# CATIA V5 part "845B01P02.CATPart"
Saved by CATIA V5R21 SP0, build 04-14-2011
Part number: 845B01P01
Bounding box of the stored display mesh (mm): x -25.75 to 25.25, y -25.549 to 25.54, z -6.5 to 6.5
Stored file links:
  C:\Users\ALI OZGUN\Desktop\alhan\845B01P02.CATPart
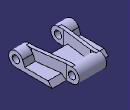
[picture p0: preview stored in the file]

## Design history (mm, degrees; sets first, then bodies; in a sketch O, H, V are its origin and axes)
Body1 (main body)
  Sketch1 on yz-plane, origin (0, 0, 0), H (0, 1, 0), V (0, 0, 1)
    construction line L1 (-19.05, 0) -> (19.05, 0)
    point P1 (-19.05, 0)
    point P2 (19.05, 0)
    line L2 (-19.05, 6.5) -> (19.05, 6.5)
    line L3 (19.05, -6.5) -> (-19.05, -6.5)
    arc A1 centre (19.05, 0) radius 6.5 from (19.05, 6.5) to (19.05, -6.5) cw
    arc A2 centre (-19.05, 0) radius 6.5 from (-19.05, -6.5) to (-19.05, 6.5) cw
    circle A3 centre (19.05, 0) radius 3.25
    circle A4 centre (-19.05, 0) radius 3.25
    distance L1 L2 = 6.5
    length L1 = 38.1
    distance P2 V = 19.05
    radius A3 = 3.25
    radius A4 = 3.25
    coincidence: P1 H
    horizontal: L1 H
    tangency: A1 L2, A2 L2, A1 L3, A2 L3
  Pad1: profile Sketch1, direction (1, 0, 0), length 76.5, mirrored extent
  Sketch2 on face of Pad1 from Sketch1.L2, origin (0, 0, 6.5), H (1, 0, 0), V (0, 1, 0)
    line L1 (38, -14) -> (64, -14)
    line L2 (64, -14) -> (64, -36.0786)
    line L3 (64, -36.0786) -> (38, -36.0786)
    line L4 (38, -36.0786) -> (38, -14)
    line L5 (-13, -14) -> (13, -14)
    line L6 (13, -14) -> (13, -36.0786)
    line L7 (13, -36.0786) -> (-13, -36.0786)
    line L8 (-13, -36.0786) -> (-13, -14)
    point P7 (13, -36.0786)
    line L9 (-64, -14) -> (-38, -14)
    line L10 (-38, -14) -> (-38, -32.269)
    line L11 (-38, -32.269) -> (-64, -32.269)
    line L12 (-64, -32.269) -> (-64, -14)
    line L13 (85.7823, 31.3847) -> (63.5, 31.3847)
    line L14 (63.5, 31.3847) -> (63.5, 14)
    line L15 (63.5, 14) -> (85.7823, 14)
    line L16 (85.7823, 14) -> (85.7823, 31.3847)
    point P17 (12.5, 31.3847)
    line L17 (12.5, 31.3847) -> (38.5, 31.3847)
    line L18 (38.5, 31.3847) -> (38.5, 14)
    line L19 (38.5, 14) -> (12.5, 14)
    line L20 (12.5, 14) -> (12.5, 31.3847)
    point P19 (38.5, 14)
    line L21 (-38.5, 32.0801) -> (-12.5, 32.0801)
    line L22 (-12.5, 32.0801) -> (-12.5, 14)
    line L23 (-12.5, 14) -> (-38.5, 14)
    line L24 (-38.5, 14) -> (-38.5, 32.0801)
    point P23 (-12.5, 14)
    line L25 (-81.4786, 33.8185) -> (-63.5, 33.8185)
    line L26 (-63.5, 33.8185) -> (-63.5, 14)
    line L27 (-63.5, 14) -> (-81.4786, 14)
    line L28 (-81.4786, 14) -> (-81.4786, 33.8185)
    point P27 (-63.5, 14)
    reference projected line E1 (76.5, 19.05) -> (76.5, -19.05) from edge [face of Pad1 from Sketch1.L2 | end face of Pad1]
    reference projected line E2 (-76.5, 19.05) -> (-76.5, -19.05) from edge [start face of Pad1 | face of Pad1 from Sketch1.L2]
    reference projected line E3 (-76.5, 19.05) -> (-76.5, -19.05) from edge [start face of Pad1 | face of Pad1 from Sketch1.L2]
    reference projected line E4 (76.5, 19.05) -> (76.5, -19.05) from edge [face of Pad1 from Sketch1.L2 | end face of Pad1]
    distance L14 E1 = 13
    distance L26 E2 = 13
    distance L12 E3 = 12.5
    distance L2 E4 = 12.5
    distance L23 L5 = 28
    distance L5 H = 14
    distance L4 L2 = 26
    distance L12 L10 = 26
    distance L10 L8 = 25
    distance L6 L4 = 25
    distance L24 L26 = 25
    distance L18 L14 = 25
    distance L26 L22 = 51
    distance L20 L18 = 26
    horizontal: L1 H, L3 H, L5 H, L7 H, L9 H, L11 H, L13 H, L15 H, L17 H, L19 H, L21 H, L23 H, L25 H, L27 H
    vertical: L2 V, L4 V, L6 V, L8 V, L10 V, L12 V, L14 V, L16 V, L18 V, L20 V, L22 V, L24 V, L26 V, L28 V
    coincidence: P7 L3, P17 L13, P19 L15, P23 L15, P27 L15, L1 L5, L9 L5
  Pocket1: profile Sketch2, direction (0, 0, -1), length 53.5
  Sketch3 on end face of Pad1, origin (76.5, 0, 0), H (0, 1, 0), V (0, 0, 1)
    projected arc E1 centre (19.05, 0) radius 6.5 from (19.05, -6.5) to (19.05, 6.5) ccw from edge [face of Pocket1 from Sketch2.L14 | face of Pad1 from Sketch1.A1]
    projected arc E2 centre (19.05, 0) radius 6.5 from (19.05, -6.5) to (13.0358, 2.4657) ccw from edge [face of Pocket1 from Sketch2.L14 | face of Pad1 from Sketch1.A1]
    point P1 (19.05, -6.5)
    projected arc E3 centre (-19.05, 0) radius 6.5 from (-19.05, 6.5) to (-19.05, -6.5) ccw from edge [face of Pad1 from Sketch1.A2 | end face of Pad1]
    projected arc E4 centre (-19.05, 0) radius 6.5 from (-13.0358, 2.4657) to (-19.05, -6.5) ccw from edge [face of Pad1 from Sketch1.A2 | end face of Pad1]
    point P4 (-19.05, -6.5)
    projected line E5 (-19.05, -6.5) -> (14, -6.5) from edge [face of Pad1 from Sketch1.L3 | end face of Pad1]
    point P5 (-19.05, -6.5)
    projected line E6 (19.05, -6.5) -> (14, -6.5) from edge [face of Pocket1 from Sketch2.L14 | face of Pad1 from Sketch1.L3]
    point P7 (19.05, -6.5)
    line L1 (-13.0358, 2.4657) -> (-11, -2.5)
    line L2 (-11, -2.5) -> (11, -2.5)
    point P10 (11, -2.5)
    line L3 (11, -2.5) -> (13.0358, 2.4657)
    distance L2 E5 = 4
    length L2 = 22
    distance P10 V = 11
    horizontal: L2 H
    tangency: L3 E1, L1 E3
    coincidence: P1 P7, P4 P5
  Pocket2: profile Sketch3, direction (-1, 0, 0), length 172.5, outer side
  Sketch4 on face of Pocket2 from Sketch3.L2, origin (0, 0, -2.5), H (1, 0, 0), V (0, 1, 0)
    projected line E1 (38, -14) -> (38, -25.55) from edge [face of Pocket2 | face of Pocket1 from Sketch2.L4]
    projected line E2 (38, -14) -> (38, -19.05) from edge [face of Pocket2 | face of Pocket1 from Sketch2.L4]
    point P1 (38, -14)
    point P2 (38, -25.55)
    projected line E3 (13, -25.55) -> (13, -14) from edge [face of Pocket2 | face of Pocket1 from Sketch2.L6]
    projected line E4 (13, -19.05) -> (13, -14) from edge [face of Pocket2 | face of Pocket1 from Sketch2.L6]
    point P3 (13, -25.55)
    point P4 (13, -14)
    projected line E5 (64, -25.55) -> (64, -14) from edge [face of Pocket2 | face of Pocket1 from Sketch2.L2]
    projected line E6 (64, -19.05) -> (64, -14) from edge [face of Pocket2 | face of Pocket1 from Sketch2.L2]
    point P5 (64, -25.55)
    point P6 (64, -14)
    projected line E7 (38.5, 14) -> (38.5, 25.55) from edge [face of Pocket2 | face of Pocket1 from Sketch2.L18]
    projected line E8 (38.5, 14) -> (38.5, 19.05) from edge [face of Pocket2 | face of Pocket1 from Sketch2.L18]
    point P7 (38.5, 14)
    point P8 (38.5, 25.55)
    projected line E9 (63.5, 14) -> (63.5, 25.55) from edge [face of Pocket1 from Sketch2.L14 | face of Pocket2]
    projected line E10 (63.5, 14) -> (63.5, 19.05) from edge [face of Pocket1 from Sketch2.L14 | face of Pocket2]
    point P9 (63.5, 14)
    point P10 (63.5, 25.55)
    projected line E11 (12.5, 25.55) -> (12.5, 14) from edge [face of Pocket2 | face of Pocket1 from Sketch2.L20]
    projected line E12 (12.5, 19.05) -> (12.5, 14) from edge [face of Pocket2 | face of Pocket1 from Sketch2.L20]
    point P11 (12.5, 25.55)
    point P12 (12.5, 14)
    offset line E13 (9.5, 25.55) -> (9.5, 14) from edge [face of Pocket2 | face of Pocket1 from Sketch2.L20]
    offset line E14 (9.5, 19.05) -> (9.5, 14) from edge [face of Pocket2 | face of Pocket1 from Sketch2.L20]
    point P13 (9.5, 25.55)
    point P14 (9.5, 14)
    offset line E15 (16, -25.55) -> (16, -14) from edge [face of Pocket2 | face of Pocket1 from Sketch2.L6]
    offset line E16 (16, -19.05) -> (16, -14) from edge [face of Pocket2 | face of Pocket1 from Sketch2.L6]
    point P15 (16, -25.55)
    point P16 (16, -14)
    offset line E17 (35, -14) -> (35, -25.55) from edge [face of Pocket2 | face of Pocket1 from Sketch2.L4]
    offset line E18 (35, -14) -> (35, -19.05) from edge [face of Pocket2 | face of Pocket1 from Sketch2.L4]
    point P17 (35, -14)
    point P18 (35, -25.55)
    offset line E19 (41.5, 14) -> (41.5, 25.55) from edge [face of Pocket2 | face of Pocket1 from Sketch2.L18]
    offset line E20 (41.5, 14) -> (41.5, 19.05) from edge [face of Pocket2 | face of Pocket1 from Sketch2.L18]
    point P19 (41.5, 14)
    point P20 (41.5, 25.55)
    offset line E21 (60.5, 14) -> (60.5, 25.55) from edge [face of Pocket1 from Sketch2.L14 | face of Pocket2]
    offset line E22 (60.5, 14) -> (60.5, 19.05) from edge [face of Pocket1 from Sketch2.L14 | face of Pocket2]
    point P21 (60.5, 14)
    point P22 (60.5, 25.55)
    offset line E23 (67, -25.55) -> (67, -14) from edge [face of Pocket2 | face of Pocket1 from Sketch2.L2]
    offset line E24 (67, -19.05) -> (67, -14) from edge [face of Pocket2 | face of Pocket1 from Sketch2.L2]
    point P23 (67, -25.55)
    point P24 (67, -14)
    line L1 (13, -14) -> (9.5, 14)
    line L2 (16, -14) -> (12.5, 14)
    line L3 (35, -14) -> (38.5, 14)
    line L4 (38, -14) -> (41.5, 14)
    line L5 (64, -14) -> (60.5, 14)
    line L6 (67, -14) -> (63.5, 14)
    projected line E25 through (0, -19.05) direction (1, 0) from axis of face of Pocket2
    projected line E26 (13, -19.05) -> (16, -19.05) from axis of face of Pocket2
    projected line E27 (64, -19.05) -> (67, -19.05) from axis of face of Pocket2
    projected line E28 (35, -19.05) -> (38, -19.05) from axis of face of Pocket2
    point P25 (-10000000, -19.05)
    point P26 (10000000, -19.05)
    point P27 (67, -19.05)
    point P28 (38, -19.05)
    point P29 (64, -19.05)
    point P30 (64, -19.05)
    point P31 (38, -19.05)
    point P32 (35, -19.05)
    point P33 (16, -19.05)
    point P34 (35, -19.05)
    point P35 (16, -19.05)
    point P36 (13, -19.05)
    point P37 (13, -19.05)
    projected line E29 through (0, 19.05) direction (1, 0) from axis of face of Pocket2
    projected line E30 (9.5, 19.05) -> (12.5, 19.05) from axis of face of Pocket2
    projected line E31 (38.5, 19.05) -> (41.5, 19.05) from axis of face of Pocket2
    projected line E32 (60.5, 19.05) -> (63.5, 19.05) from axis of face of Pocket2
    point P38 (-10000000, 19.05)
    point P39 (10000000, 19.05)
    point P40 (63.5, 19.05)
    point P41 (9.5, 19.05)
    point P42 (9.5, 19.05)
    point P43 (12.5, 19.05)
    point P44 (12.5, 19.05)
    point P45 (38.5, 19.05)
    point P46 (38.5, 19.05)
    point P47 (41.5, 19.05)
    point P48 (60.5, 19.05)
    point P49 (41.5, 19.05)
    point P50 (60.5, 19.05)
    point P51 (-10000000, -19.05)
    point P52 (10000000, -19.05)
    point P53 (-10000000, 19.05)
    point P54 (10000000, 19.05)
    construction line L7 through (0, -19.05) direction (-1, 0)
    construction line L8 through (0, 19.05) direction (-1, 0)
    point P55 (-10000000, -19.05)
    point P56 (10000000, -19.05)
    point P57 (-16, -19.05)
    point P58 (-13, -19.05)
    point P59 (-67, -19.05)
    point P60 (-64, -19.05)
    point P61 (-38, -19.05)
    point P62 (-35, -19.05)
    point P63 (-38, -25.55)
    point P64 (-38, -14)
    point P65 (-38, -19.05)
    point P66 (-13, -14)
    point P67 (-13, -25.55)
    point P68 (-13, -19.05)
    point P69 (-64, -14)
    point P70 (-64, -25.55)
    point P71 (-64, -19.05)
    point P72 (-38.5, 25.55)
    point P73 (-38.5, 14)
    point P74 (-38.5, 19.05)
    point P75 (-63.5, 25.55)
    point P76 (-63.5, 14)
    point P77 (-63.5, 19.05)
    point P78 (-12.5, 14)
    point P79 (-12.5, 25.55)
    point P80 (-12.5, 19.05)
    point P81 (-9.5, 14)
    point P82 (-9.5, 25.55)
    point P83 (-9.5, 19.05)
    point P84 (-16, -14)
    point P85 (-16, -25.55)
    point P86 (-16, -19.05)
    point P87 (-35, -25.55)
    point P88 (-35, -14)
    point P89 (-35, -19.05)
    point P90 (-41.5, 25.55)
    point P91 (-41.5, 14)
    point P92 (-41.5, 19.05)
    point P93 (-60.5, 25.55)
    point P94 (-60.5, 14)
    point P95 (-60.5, 19.05)
    point P96 (-67, -14)
    point P97 (-67, -25.55)
    line L9 (-13, -14) -> (-9.5, 14)
    line L10 (-16, -14) -> (-12.5, 14)
    line L11 (-35, -14) -> (-38.5, 14)
    line L12 (-38, -14) -> (-41.5, 14)
    line L13 (-64, -14) -> (-60.5, 14)
    line L14 (-67, -14) -> (-63.5, 14)
    point P98 (-10000000, 19.05)
    point P99 (10000000, 19.05)
    point P100 (-12.5, 19.05)
    point P101 (-9.5, 19.05)
    point P102 (-41.5, 19.05)
    point P103 (-38.5, 19.05)
    point P104 (-60.5, 19.05)
    construction line L15 through (0, -19.05) direction (-1, 0)
    line L16 (-13, -19.05) -> (-16, -19.05)
    line L17 (-64, -19.05) -> (-67, -19.05)
    line L18 (-35, -19.05) -> (-38, -19.05)
    construction line L19 (-38, -14) -> (-38, -25.55)
    line L20 (-38, -14) -> (-38, -19.05)
    construction line L21 (-13, -25.55) -> (-13, -14)
    line L22 (-13, -19.05) -> (-13, -14)
    construction line L23 (-64, -25.55) -> (-64, -14)
    line L24 (-64, -19.05) -> (-64, -14)
    construction line L25 (-38.5, 14) -> (-38.5, 25.55)
    line L26 (-38.5, 14) -> (-38.5, 19.05)
    construction line L27 (-63.5, 14) -> (-63.5, 25.55)
    line L28 (-63.5, 14) -> (-63.5, 19.05)
    construction line L29 (-12.5, 25.55) -> (-12.5, 14)
    line L30 (-12.5, 19.05) -> (-12.5, 14)
    construction line L31 (-9.5, 25.55) -> (-9.5, 14)
    line L32 (-9.5, 19.05) -> (-9.5, 14)
    construction line L33 (-16, -25.55) -> (-16, -14)
    line L34 (-16, -19.05) -> (-16, -14)
    construction line L35 (-35, -14) -> (-35, -25.55)
    line L36 (-35, -14) -> (-35, -19.05)
    construction line L37 (-41.5, 14) -> (-41.5, 25.55)
    line L38 (-41.5, 14) -> (-41.5, 19.05)
    construction line L39 (-60.5, 14) -> (-60.5, 25.55)
    line L40 (-60.5, 14) -> (-60.5, 19.05)
    construction line L41 (-67, -25.55) -> (-67, -14)
    line L42 (-67, -19.05) -> (-67, -14)
    construction line L43 through (0, 19.05) direction (-1, 0)
    line L44 (-9.5, 19.05) -> (-12.5, 19.05)
    line L45 (-38.5, 19.05) -> (-41.5, 19.05)
    line L46 (-60.5, 19.05) -> (-63.5, 19.05)
    parallelism: L2 L1, L4 L3
    coincidence: E1 P28, E5 P29, E25 P30, E25 P31, E25 P32, E15 P33, E17 P34, E25 P35, E25 P36, E3 P37, E13 P41, E29 P42, E29 P43, E11 P44, E7 P45, E29 P46, E29 P47, E29 P48, E19 P49, E21 P50, P28 P31, P29 P30, P32 P34, P33 P35, P36 P37, P41 P42, P43 P44, P45 P46, P47 P49, P48 P50
    symmetry: P26 P51 V, P25 P52 V, E25 L7 V, P39 P53 V, P38 P54 V, E29 L8 V, P26 P55 V, P25 P56 V, P33 P57 V, P37 P58 V, P27 P59 V, P29 P60 V, P28 P61 V, P34 P62 V, E25 L15 V, P2 P63 V, P1 P64 V, P31 P65 V, E1 L19 V, P4 P66 V, P3 P67 V, P36 P68 V, E3 L21 V, P6 P69 V, P5 P70 V, P30 P71 V, E5 L23 V, P8 P72 V, P7 P73 V, P46 P74 V, E7 L25 V, P10 P75 V, P9 P76 V, P40 P77 V, E9 L27 V, P12 P78 V, P11 P79 V, P43 P80 V, E11 L29 V, P14 P81 V, P13 P82 V, P42 P83 V, E13 L31 V, P16 P84 V, P15 P85 V, P35 P86 V, E15 L33 V, P18 P87 V, P17 P88 V, P32 P89 V, E17 L35 V, P20 P90 V, P19 P91 V, P47 P92 V, E19 L37 V, P22 P93 V, P21 P94 V, P48 P95 V, E21 L39 V, P24 P96 V, P23 P97 V, E23 L41 V, L1 L9 V, L2 L10 V, L3 L11 V, L4 L12 V, L5 L13 V, L6 L14 V, P39 P98 V, P38 P99 V, P44 P100 V, P41 P101 V, P49 P102 V, P45 P103 V, P50 P104 V, E29 L43 V, E25 L18 V, E25 L17 V, E25 L16 V, E1 L20 V, E3 L22 V, E5 L24 V, E7 L26 V, E9 L28 V, E11 L30 V, E13 L32 V, E15 L34 V, E17 L36 V, E19 L38 V, E21 L40 V, E23 L42 V, E29 L46 V, E29 L45 V, E29 L44 V
  Pad2: profile Sketch4, direction (0, 0, 1), length 9
  Sketch5 on yz-plane, origin (0, 0, 0), H (0, 1, 0), V (0, 0, 1)
    projected circle E1 centre (-19.05, 0) radius 3.25 from edge [end face of Pad1 | face of Pad1 from Sketch1.A4]
    circle A1 centre (19.05, 0) radius 3.25
    reference projected circle E2 centre (19.05, 0) radius 3.25 from edge [face of Pad1 from Sketch1.A3 | face of Pad2]
    coincidence: A1 E2
  Pocket3: profile Sketch5, direction (-1, 0, 0), length 95, mirrored extent
  RemoveFace1: RemoveFaces (face of Pocket2 from Sketch3.L3; face of Pocket2; face of Pocket2 from Sketch3.L3; face of Pocket2; face of Pocket2 from Sketch3.L1; face of Pocket2; face of Pocket2 from Sketch3.L1; face of Pocket2; face of Pocket2; face of Pocket2; face of Pocket2; face of Pocket2 from Sketch3.L3; face of Pocket2 from Sketch3.L3; face of Pocket2 from Sketch3.L1)
  Chamfer1: length 4, angle 45, on edge [face of Pocket1 from Sketch2.L27 | face of Pocket2 from Sketch3.L2]; edge [face of Pocket1 from Sketch2.L9 | face of Pocket2 from Sketch3.L2]; edge [face of Pocket1 from Sketch2.L19 | face of Pocket2 from Sketch3.L2]; edge [face of Pocket1 from Sketch2.L5 | face of Pocket2 from Sketch3.L2]; edge [face of Pocket1 from Sketch2.L1 | face of Pocket2 from Sketch3.L2]; edge [face of Pocket1 from Sketch2.L15 | face of Pocket2 from Sketch3.L2]; edge [face of Pocket1 from Sketch2.L23 | face of Pocket2 from Sketch3.L2]
  Sketch6 on face of Pocket2, origin (0, 0, -6.5), H (1, 0, 0), V (0, -1, 0)
    line L1 (-25.75, 44.4621) -> (25.25, 44.4621)
    line L2 (25.25, 44.4621) -> (25.25, -35.3991)
    line L3 (25.25, -35.3991) -> (-25.75, -35.3991)
    line L4 (-25.75, -35.3991) -> (-25.75, 44.4621)
    distance L4 L2 = 51
    distance L4 V = 25.75
    horizontal: L1 H, L3 H
    vertical: L2 V, L4 V
  Pocket4: profile Sketch6, direction (0, 0, 1), length 25, mirrored extent, outer side
Body2
  Solid1: linked copy from another document
  Translate1: Direction zx-plane, Length 38.1, ToTransfor Solid1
